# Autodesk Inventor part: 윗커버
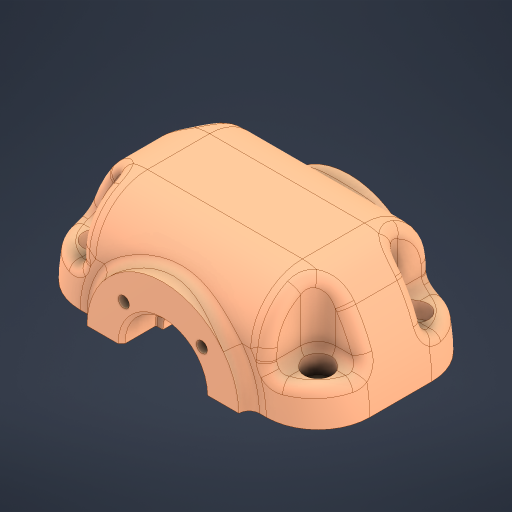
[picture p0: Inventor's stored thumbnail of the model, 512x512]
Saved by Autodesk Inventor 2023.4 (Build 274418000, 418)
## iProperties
Created: 2024-05
Part Number: 윗커버
Material: 알루미늄 6061
Document SubType Name: Modeling
Designer: Edu03
Density: 2.7 g/cm^3
Appearance: 기본값
Sending System: Autodesk Inventor 2025
Preprocessor: ST-DEVELOPER v20
Author: jhkim
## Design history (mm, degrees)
node "윗커버1"
node "솔리드2"
node "솔리드1"
